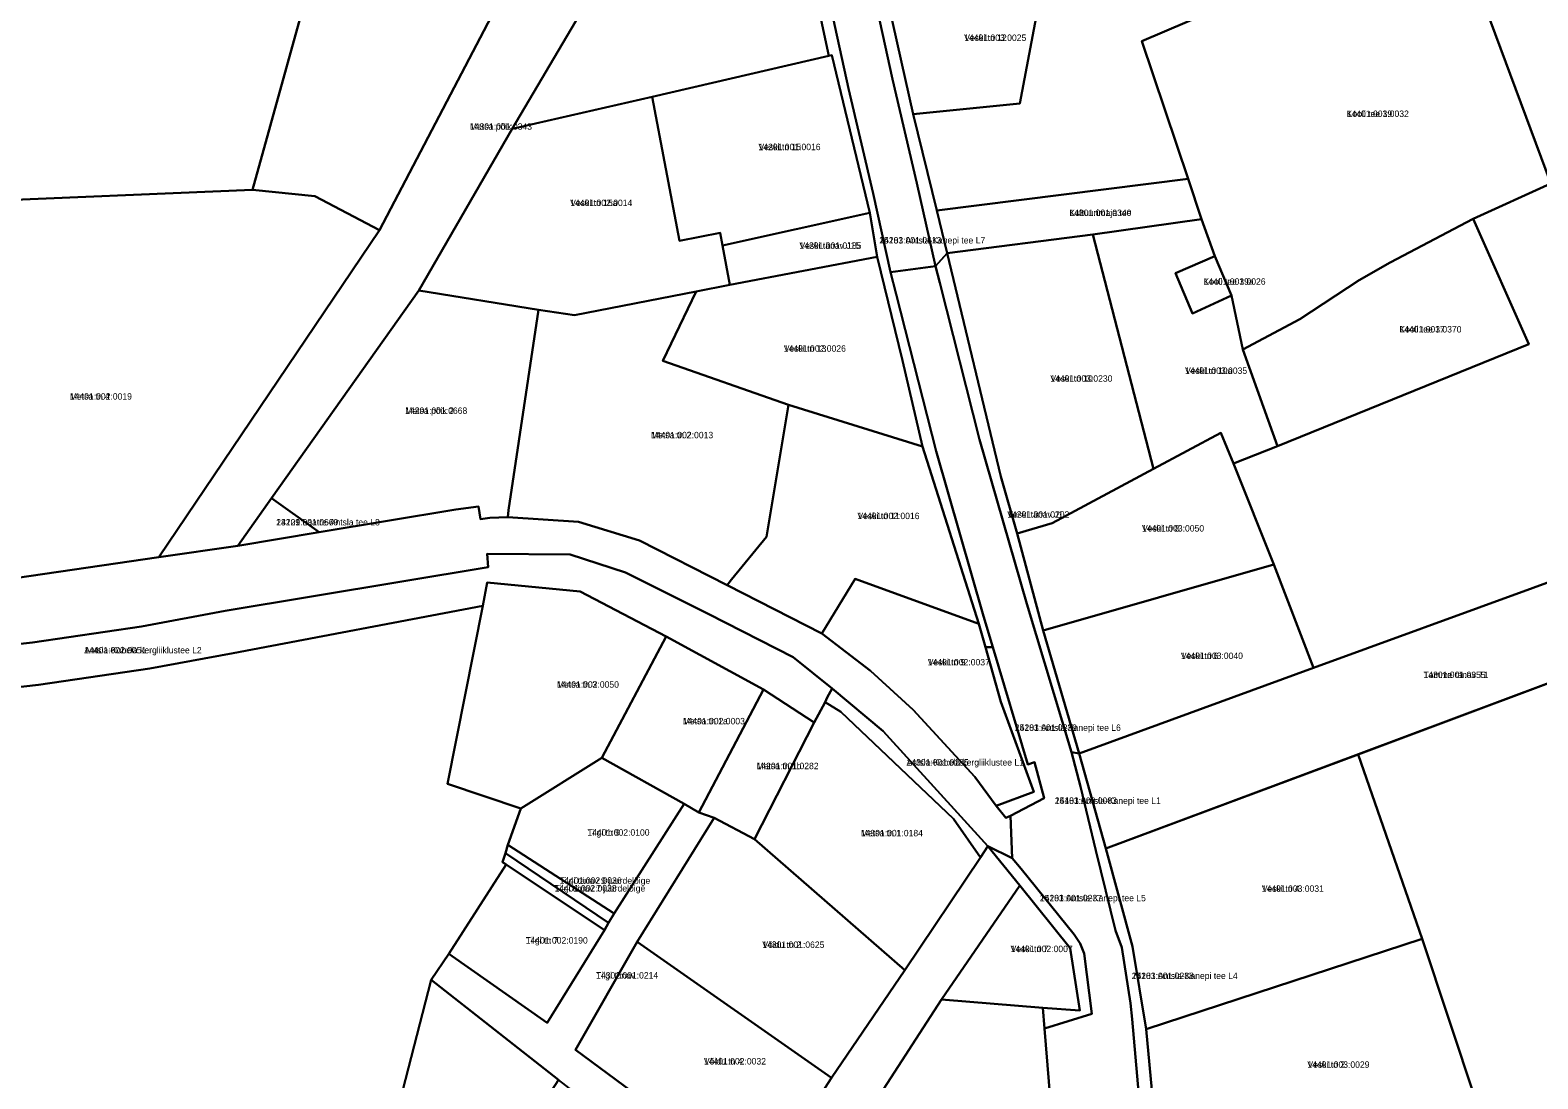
# Model space of a CAD drawing. Extents: x 640657 to 665127, y 6395726 to 6426831.
# Drawn here: x 649927.4 to 650279.6, y 6412630.2 to 6412875.2 of the extents above; entities that cross this region are included whole.
import ezdxf

# ---------------------------------------------------------------- set-up
doc = ezdxf.new("R2010")
doc.units = 0
for name, color, linetype in [('L_AADRESS', 7, 'Continuous'), ('PIIR', 7, 'Continuous'), ('TUNNUS', 7, 'Continuous')]:
    doc.layers.add(name, color=color, linetype=linetype)

msp = doc.modelspace()

# ---------------------------------------------------------------- linework, layer by layer
at = {"layer": 'PIIR'}
for points in [[(650075.82, 6413194.87), (650035.9, 6413038.33), (650029.91, 6413017.75), (650013.12, 6412950.76), (650011.32, 6412943.44), (649995.48, 6412896.01), (649979.35, 6412837.85), (649912.58, 6412835.05), (649873.8, 6412751.6), (649783.99, 6412761.55), (649725.8, 6412733.89), (649702.61, 6412730.39), (649660.39, 6412727.03), (649637.16, 6412726.43), (649580.19, 6412722.52), (649451.05, 6412725.29)], [(650119.56, 6412906.45), (650128.85, 6412863.68), (650134.56, 6412839.42), (650138.9, 6412820.05), (650128.41, 6412818.65), (650124.34, 6412836.99), (650118.56, 6412861.55), (650109.28, 6412904.36)], [(650167.51, 6412603.89), (650164.41, 6412641.93), (650175.42, 6412645.39), (650173.68, 6412659.44), (650172.69, 6412661.79), (650171.28, 6412663.92), (650158.92, 6412679.22), (650156.86, 6412681.77), (650156.4, 6412691.61), (650164.33, 6412695.72), (650162.03, 6412704.13), (650160.46, 6412703.62), (650152.3, 6412731.02), (650150.14, 6412738.26), (650139.04, 6412776.8), (650129.76, 6412813.51), (650128.41, 6412818.65), (650138.9, 6412820.05), (650139.93, 6412816.14), (650149.17, 6412779.54), (650160.23, 6412741.16), (650170.66, 6412706.52), (650172.79, 6412698.44), (650176.35, 6412683.53), (650180.97, 6412664.81), (650182.46, 6412660.87), (650184.49, 6412647.84), (650184.85, 6412644.1), (650188.12, 6412606.82)], [(649873.8, 6412739.85), (649957.5, 6412752.07), (649975.94, 6412754.7), (649994.97, 6412757.85), (650026.85, 6412763.16), (650032.17, 6412763.89), (650032.64, 6412760.94), (650034.81, 6412761.23), (650038.99, 6412761.42), (650055.51, 6412760.3), (650069.76, 6412755.92), (650090.24, 6412745.54), (650112.35, 6412734.21), (650123.75, 6412725.48), (650133.73, 6412716.35), (650148.13, 6412700.75), (650153.12, 6412693.95), (650155.31, 6412691.13), (650156.4, 6412691.61), (650156.86, 6412681.77), (650151.18, 6412684.5), (650126.68, 6412711.41), (650114.75, 6412721.36), (650105.7, 6412728.7), (650085.96, 6412738.72), (650066.5, 6412748.45), (650053.56, 6412752.69), (650034.17, 6412752.83), (650034.44, 6412749.68), (649972.99, 6412739.53), (649953.48, 6412735.82), (649927.99, 6412732.11), (649894.7, 6412728.35)], [(649894.7, 6412728.35), (649927.99, 6412732.11), (649953.48, 6412735.82), (649972.99, 6412739.53), (650034.44, 6412749.68), (650034.17, 6412752.83), (650053.56, 6412752.69), (650066.5, 6412748.45), (650085.96, 6412738.72), (650105.7, 6412728.7), (650114.75, 6412721.36), (650113.65, 6412719.28), (650113.12, 6412718.15), (650110.61, 6412713.42), (650098.77, 6412721.13), (650075.98, 6412733.48), (650055.9, 6412743.99), (650034.19, 6412746.13), (650033.2, 6412740.7), (649974.9, 6412729.6), (649955.4, 6412726), (649929.4, 6412722.2), (649895.8, 6412718.4)], [(649798.2, 6412604.7), (649792.4, 6412645.6), (649780.3, 6412706.3), (649801.1, 6412708.5), (649832.6, 6412711.8), (649863.2, 6412714.4), (649895.8, 6412718.4), (649929.4, 6412722.2), (649955.4, 6412726), (649974.9, 6412729.6), (650033.2, 6412740.7), (650024.96, 6412699.1), (650042.08, 6412693.34), (650039.04, 6412684.84), (650038.46, 6412682.93), (650037.78, 6412680.8), (650038.62, 6412680.27), (650025.2, 6412659.37), (650021.1, 6412653.3), (650007.16, 6412599.18)], [(650098.19, 6412604.91), (650114.66, 6412630.41), (650131.77, 6412655.53), (650149.42, 6412681.91), (650151.18, 6412684.5), (650158.62, 6412675.31), (650140.29, 6412648.7), (650110.64, 6412602.88)]]:
    msp.add_lwpolyline(points, dxfattribs=at)
for points in [[(650138.9, 6412820.05), (650134.56, 6412839.42), (650128.85, 6412863.68), (650119.56, 6412906.45), (650114.91, 6412933.04), (650113.52, 6412949.33), (650114.58, 6412966.11), (650117.14, 6412962.99), (650116.4, 6412957), (650116.8, 6412938.7), (650127.07, 6412885.11), (650133.7, 6412855.52), (650139.23, 6412833.01), (650141.67, 6412823.06)], [(650160.6, 6412948.4), (650261.9, 6412914.8), (650270.8, 6412911.5), (650272.9, 6412909.24), (650187.12, 6412872.57), (650197.94, 6412840.41), (650139.23, 6412833.01), (650133.7, 6412855.52), (650158.62, 6412858.03), (650164.6, 6412889.76), (650172.9, 6412890.8)], [(650100.12, 6412934.32), (650099.26, 6412940.85), (650103.52, 6412943.21), (650104.49, 6412931.77), (650109.28, 6412904.36), (650118.56, 6412861.55), (650124.34, 6412836.99), (650128.41, 6412818.65), (650129.76, 6412813.51), (650139.04, 6412776.8), (650150.14, 6412738.26), (650152.3, 6412731.02), (650150.59, 6412731), (650149.05, 6412736.51), (650135.86, 6412777.87), (650131.21, 6412798), (650125.27, 6412822.22), (650123.55, 6412832.47), (650114.73, 6412869.35), (650114.02, 6412869.15), (650102.81, 6412921.46)], [(649957.5, 6412752.07), (650009.04, 6412828.45), (650044.8, 6412896.8), (650061.49, 6412913.16), (650083.62, 6412924.59), (650091.47, 6412929.42), (650100.12, 6412934.32), (650102.81, 6412921.46), (650064.61, 6412893.83), (650040.04, 6412852.08), (650018.22, 6412814.34), (649983.85, 6412765.83), (649975.94, 6412754.7)], [(649995.47, 6412895.99), (650024.41, 6412888.09), (650040.26, 6412935.52), (650064.09, 6412929.28), (650061.49, 6412913.16), (650044.8, 6412896.8), (650009.04, 6412828.45), (649993.91, 6412836.34), (649979.35, 6412837.85)], [(650102.81, 6412921.46), (650114.02, 6412869.15), (650072.73, 6412859.57), (650040.04, 6412852.08), (650064.61, 6412893.83)], [(650210.67, 6412800.52), (650208.07, 6412813.16), (650204.13, 6412822.35), (650201.08, 6412831.03), (650197.94, 6412840.41), (650187.12, 6412872.57), (650272.9, 6412909.24), (650282.26, 6412886.17), (650267.38, 6412880.34), (650282.69, 6412839.36), (650264.5, 6412831.05), (650245.1, 6412820.91), (650237.85, 6412816.79), (650224.05, 6412807.61)], [(650127.07, 6412885.11), (650164.6, 6412889.76), (650158.62, 6412858.03), (650133.7, 6412855.52)], [(650267.38, 6412880.34), (650282.26, 6412886.17), (650285.9, 6412881.2), (650299.3, 6412846.7), (650282.69, 6412839.36)], [(650079.11, 6412825.91), (650072.73, 6412859.57), (650114.02, 6412869.15), (650114.73, 6412869.35), (650123.55, 6412832.47), (650089.18, 6412824.88), (650088.59, 6412827.84)], [(650072.73, 6412859.57), (650079.11, 6412825.91), (650088.59, 6412827.84), (650089.18, 6412824.88), (650090.88, 6412815.7), (650082.98, 6412814.1), (650054.58, 6412808.56), (650046.22, 6412809.84), (650018.22, 6412814.34), (650040.04, 6412852.08)], [(650208.51, 6412773.92), (650218.79, 6412778), (650277.53, 6412801.82), (650264.5, 6412831.05), (650282.69, 6412839.36), (650299.3, 6412846.7), (650329.8, 6412763.6), (650227.2, 6412726.23), (650217.94, 6412750.3)], [(650139.23, 6412833.01), (650197.94, 6412840.41), (650201.08, 6412831.03), (650175.65, 6412827.44), (650141.67, 6412823.06)], [(649912.58, 6412835.05), (649979.35, 6412837.85), (649993.91, 6412836.34), (650009.04, 6412828.45), (649957.5, 6412752.07), (649873.8, 6412739.85), (649873.8, 6412751.6)], [(650089.18, 6412824.88), (650123.55, 6412832.47), (650125.27, 6412822.22), (650090.88, 6412815.7)], [(650201.08, 6412831.03), (650204.13, 6412822.35), (650194.96, 6412818.35), (650198.97, 6412808.98), (650208.07, 6412813.16), (650210.67, 6412800.52), (650215.53, 6412787.06), (650218.79, 6412778), (650208.51, 6412773.92), (650205.54, 6412781.12), (650189.82, 6412772.68), (650175.65, 6412827.44)], [(650215.53, 6412787.06), (650210.67, 6412800.52), (650224.05, 6412807.61), (650237.85, 6412816.79), (650245.1, 6412820.91), (650264.5, 6412831.05), (650277.53, 6412801.82), (650218.79, 6412778)], [(650157.96, 6412757.58), (650154.19, 6412770.87), (650141.67, 6412823.06), (650175.65, 6412827.44), (650189.82, 6412772.68), (650166.14, 6412760.01)], [(650082.98, 6412814.1), (650090.88, 6412815.7), (650125.27, 6412822.22), (650131.21, 6412798), (650135.86, 6412777.87), (650104.56, 6412787.65), (650075.22, 6412797.9)], [(650172.47, 6412706.22), (650170.66, 6412706.52), (650160.23, 6412741.16), (650149.17, 6412779.54), (650139.93, 6412816.14), (650138.9, 6412820.05), (650141.67, 6412823.06), (650154.19, 6412770.87), (650157.96, 6412757.58), (650164.09, 6412734.94)], [(650194.96, 6412818.35), (650204.13, 6412822.35), (650208.07, 6412813.16), (650198.97, 6412808.98)], [(649983.85, 6412765.83), (650018.22, 6412814.34), (650046.22, 6412809.84), (650039.18, 6412763.06), (650038.99, 6412761.42), (650034.81, 6412761.23), (650032.64, 6412760.94), (650032.17, 6412763.89), (650026.85, 6412763.16), (649994.97, 6412757.85)], [(650054.58, 6412808.56), (650082.98, 6412814.1), (650075.22, 6412797.9), (650104.56, 6412787.65), (650099.41, 6412756.83), (650091.27, 6412746.81), (650090.24, 6412745.54), (650069.76, 6412755.92), (650055.51, 6412760.3), (650038.99, 6412761.42), (650039.18, 6412763.06), (650046.22, 6412809.84)], [(650090.24, 6412745.54), (650091.27, 6412746.81), (650099.41, 6412756.83), (650104.56, 6412787.65), (650135.86, 6412777.87), (650149.05, 6412736.51), (650120.14, 6412746.95), (650112.35, 6412734.21)], [(650157.96, 6412757.58), (650166.14, 6412760.01), (650189.82, 6412772.68), (650205.54, 6412781.12), (650208.51, 6412773.92), (650217.94, 6412750.3), (650164.09, 6412734.94)], [(649975.94, 6412754.7), (649983.85, 6412765.83), (649994.97, 6412757.85)], [(650172.47, 6412706.22), (650227.2, 6412726.23), (650329.8, 6412763.6), (650337.4, 6412743.2), (650331.86, 6412741.39), (650303.9, 6412730.8), (650237.7, 6412706), (650178.71, 6412684.02)], [(650164.09, 6412734.94), (650217.94, 6412750.3), (650227.2, 6412726.23), (650172.47, 6412706.22)], [(650024.96, 6412699.1), (650033.2, 6412740.7), (650034.19, 6412746.13), (650055.9, 6412743.99), (650075.98, 6412733.48), (650061.01, 6412705.16), (650042.08, 6412693.34)], [(650112.35, 6412734.21), (650120.14, 6412746.95), (650149.05, 6412736.51), (650150.59, 6412731), (650154.16, 6412718.26), (650161.87, 6412697.2), (650153.12, 6412693.95), (650148.13, 6412700.75), (650133.73, 6412716.35), (650123.75, 6412725.48)], [(650075.98, 6412733.48), (650098.77, 6412721.13), (650083.6, 6412692.36), (650080.22, 6412694.46), (650061.01, 6412705.16)], [(650156.4, 6412691.61), (650155.31, 6412691.13), (650153.12, 6412693.95), (650161.87, 6412697.2), (650154.16, 6412718.26), (650150.59, 6412731), (650152.3, 6412731.02), (650160.46, 6412703.62), (650162.03, 6412704.13), (650164.33, 6412695.72)], [(650237.63, 6412705.98), (650303.88, 6412730.75), (650316.1, 6412701.52), (650316.75, 6412691.86), (650305.68, 6412683.87), (650314.59, 6412660.95), (650328.64, 6412621.96), (650285.03, 6412605.8), (650278.75, 6412623.58), (650267.2, 6412619.43), (650265.16, 6412625.12), (650252.6, 6412662.9)], [(650098.77, 6412721.13), (650110.61, 6412713.42), (650096.64, 6412686.16), (650087.19, 6412691.13), (650083.6, 6412692.36)], [(650113.65, 6412719.28), (650114.75, 6412721.36), (650126.68, 6412711.41), (650151.18, 6412684.5), (650149.42, 6412681.91), (650143.11, 6412690.91), (650116.78, 6412715.91), (650113.12, 6412718.15)], [(650110.61, 6412713.42), (650113.12, 6412718.15), (650116.78, 6412715.91), (650143.11, 6412690.91), (650149.42, 6412681.91), (650131.77, 6412655.53), (650096.64, 6412686.16)], [(650196.38, 6412544.58), (650192.03, 6412558.48), (650191.24, 6412560.88), (650190.3, 6412567.31), (650188.12, 6412606.82), (650184.85, 6412644.1), (650184.49, 6412647.84), (650182.46, 6412660.87), (650180.97, 6412664.81), (650176.35, 6412683.53), (650172.79, 6412698.44), (650170.66, 6412706.52), (650172.47, 6412706.22), (650178.71, 6412684.02), (650184.97, 6412661.12), (650188.11, 6412641.75), (650191.8, 6412602.62), (650191.64, 6412596.08), (650194.33, 6412558.97), (650198.85, 6412545.44)], [(650178.71, 6412684.02), (650237.63, 6412705.98), (650252.6, 6412662.9), (650188.11, 6412641.75), (650184.97, 6412661.12)], [(650042.08, 6412693.34), (650061.01, 6412705.16), (650080.22, 6412694.46), (650063.83, 6412668.79), (650039.04, 6412684.84)], [(650050.88, 6412629.95), (650021.1, 6412653.3), (650025.2, 6412659.37), (650048.24, 6412643.28), (650061.58, 6412664.94), (650062.55, 6412666.63), (650063.83, 6412668.79), (650080.22, 6412694.46), (650083.6, 6412692.36), (650087.19, 6412691.13), (650069.2, 6412662.15), (650054.81, 6412636.95), (650098.19, 6412604.91), (650094.03, 6412597.95), (650067.08, 6412617.43)], [(650069.2, 6412662.15), (650087.19, 6412691.13), (650096.64, 6412686.16), (650131.77, 6412655.53), (650114.66, 6412630.41)], [(650039.04, 6412684.84), (650063.83, 6412668.79), (650062.55, 6412666.63), (650038.46, 6412682.93)], [(650172.63, 6412646.13), (650170.39, 6412660.73), (650158.62, 6412675.31), (650151.18, 6412684.5), (650156.86, 6412681.77), (650158.92, 6412679.22), (650171.28, 6412663.92), (650172.69, 6412661.79), (650173.68, 6412659.44), (650175.42, 6412645.39), (650164.41, 6412641.93), (650164, 6412646.78)], [(650038.46, 6412682.93), (650062.55, 6412666.63), (650061.58, 6412664.94), (650038.62, 6412680.27), (650037.78, 6412680.8)], [(650048.24, 6412643.28), (650025.2, 6412659.37), (650038.62, 6412680.27), (650061.58, 6412664.94)], [(650158.62, 6412675.31), (650170.39, 6412660.73), (650172.63, 6412646.13), (650164, 6412646.78), (650140.29, 6412648.7)], [(650069.2, 6412662.15), (650114.66, 6412630.41), (650098.19, 6412604.91), (650054.81, 6412636.95)], [(650188.11, 6412641.75), (650252.6, 6412662.9), (650265.16, 6412625.12), (650231.95, 6412612.47), (650191.8, 6412602.62)], [(650007.16, 6412599.18), (650021.1, 6412653.3), (650050.88, 6412629.95), (650023.97, 6412588.36)], [(650110.64, 6412602.88), (650140.29, 6412648.7), (650164, 6412646.78), (650164.41, 6412641.93), (650167.51, 6412603.89), (650163, 6412603.82)]]:
    msp.add_lwpolyline(points, close=True, dxfattribs=at)

# ---------------------------------------------------------------- texts
at = {"layer": 'L_AADRESS'}
for s, p in [('Veski tn 12', (650145.62, 6412872.64)), ('Metsa põik', (650030.16, 6412851.9)), ('Kooli tee 19', (650234.98, 6412854.88)), ('Veski tn 15', (650097.57, 6412847.12)), ('Veski tn 15a', (650053.59, 6412834.07)), ('Kultuurimaja tee', (650170.19, 6412831.74)), ('Veski tänav J15', (650107.14, 6412824.08)), ('25183 Antsla-Kanepi tee L7', (650125.78, 6412825.32)), ('Kooli tee 19a', (650201.52, 6412815.68)), ('Kooli tee 17', (650247.28, 6412804.53)), ('Veski tn 13', (650103.48, 6412800.04)), ('Veski tn 10', (650165.75, 6412793.03)), ('Veski tn 10a', (650197.22, 6412794.86)), ('Metsa tn 4', (649936.71, 6412788.85)), ('Metsa põik 2', (650015.04, 6412785.52)), ('Metsa tn 2', (650072.48, 6412779.82)), ('Veski tn 11', (650120.68, 6412760.93)), ('Veski tänav J1', (650155.68, 6412761.27)), ('23129 Laatre-Antsla tee L8', (649984.92, 6412759.46)), ('Veski tn 8', (650187.16, 6412758.03)), ('Antsla-Kobela kergliiklustee L2', (649940.08, 6412729.57)), ('Veski tn 9', (650137.11, 6412726.76)), ('Veski tn 6', (650196.23, 6412728.26)), ('Metsa tn 3', (650050.47, 6412721.55)), ('Tamme tänav T1', (650252.91, 6412723.81)), ('Metsa tn 1a', (650079.89, 6412713)), ('25183 Antsla-Kanepi tee L6', (650157.46, 6412711.47)), ('Metsa tn 1b', (650097.11, 6412702.52)), ('Antsla-Kobela kergliiklustee L1', (650132.15, 6412703.36)), ('25183 Antsla-Kanepi tee L1', (650166.79, 6412694.41)), ('Tiigi tn 9', (650057.62, 6412686.98)), ('Metsa tn 1', (650121.48, 6412686.84)), ('Tiigi tänav 9 juurdelõige', (650051.1, 6412675.74)), ('Tiigi tänav 7 juurdelõige', (650049.93, 6412673.94)), ('Veski tn 4', (650215.14, 6412673.87)), ('25183 Antsla-Kanepi tee L5', (650163.3, 6412671.66)), ('Tiigi tn 7', (650043.19, 6412661.78)), ('Võidu tn 2', (650098.47, 6412660.77)), ('Veski tn 7', (650156.46, 6412659.78)), ('Tiigi tänav', (650059.64, 6412653.61)), ('25183 Antsla-Kanepi tee L4', (650184.75, 6412653.5)), ('Võidu tn 4', (650084.82, 6412633.53)), ('Veski tn 2', (650225.79, 6412632.76))]:
    msp.add_text(s, height=1.5, dxfattribs=at).set_placement(p)
at = {"layer": 'TUNNUS'}
for s, p in [('14401:003:0025', (650145.62, 6412872.64)), ('14301:001:0343', (650030.16, 6412851.9)), ('14401:003:0032', (650234.98, 6412854.88)), ('14201:001:0016', (650097.57, 6412847.12)), ('14401:002:0014', (650053.59, 6412834.07)), ('14301:001:0340', (650170.19, 6412831.74)), ('14201:001:0185', (650107.14, 6412824.08)), ('14201:001:0413', (650125.78, 6412825.32)), ('14401:003:0026', (650201.52, 6412815.68)), ('14401:003:0370', (650247.28, 6412804.53)), ('14401:002:0026', (650103.48, 6412800.04)), ('14401:003:0230', (650165.75, 6412793.03)), ('14401:003:0035', (650197.22, 6412794.86)), ('14401:002:0019', (649936.71, 6412788.85)), ('14201:001:0668', (650015.04, 6412785.52)), ('14401:002:0013', (650072.48, 6412779.82)), ('14401:002:0016', (650120.68, 6412760.93)), ('14201:001:0202', (650155.68, 6412761.27)), ('14201:001:0669', (649984.92, 6412759.46)), ('14401:003:0050', (650187.16, 6412758.03)), ('14401:002:0051', (649940.08, 6412729.57)), ('14401:002:0037', (650137.11, 6412726.76)), ('14401:003:0040', (650196.23, 6412728.26)), ('14401:002:0050', (650050.47, 6412721.55)), ('14301:001:0355', (650252.91, 6412723.81)), ('14401:002:0003', (650079.89, 6412713)), ('14201:001:0239', (650157.46, 6412711.47)), ('14201:001:0282', (650097.11, 6412702.52)), ('14301:001:0185', (650132.15, 6412703.36)), ('14401:003:0003', (650166.79, 6412694.41)), ('14401:002:0100', (650057.62, 6412686.98)), ('14301:001:0184', (650121.48, 6412686.84)), ('14401:002:0036', (650051.1, 6412675.74)), ('14401:002:0038', (650049.93, 6412673.94)), ('14401:003:0031', (650215.14, 6412673.87)), ('14201:001:0237', (650163.3, 6412671.66)), ('14401:002:0190', (650043.19, 6412661.78)), ('14301:001:0625', (650098.47, 6412660.77)), ('14401:002:0007', (650156.46, 6412659.78)), ('14301:001:0214', (650059.64, 6412653.61)), ('14201:001:0238', (650184.75, 6412653.5)), ('14401:002:0032', (650084.82, 6412633.53)), ('14401:003:0029', (650225.79, 6412632.76))]:
    msp.add_text(s, height=1.5, dxfattribs=at).set_placement(p)

doc.saveas('drawing.dxf')
